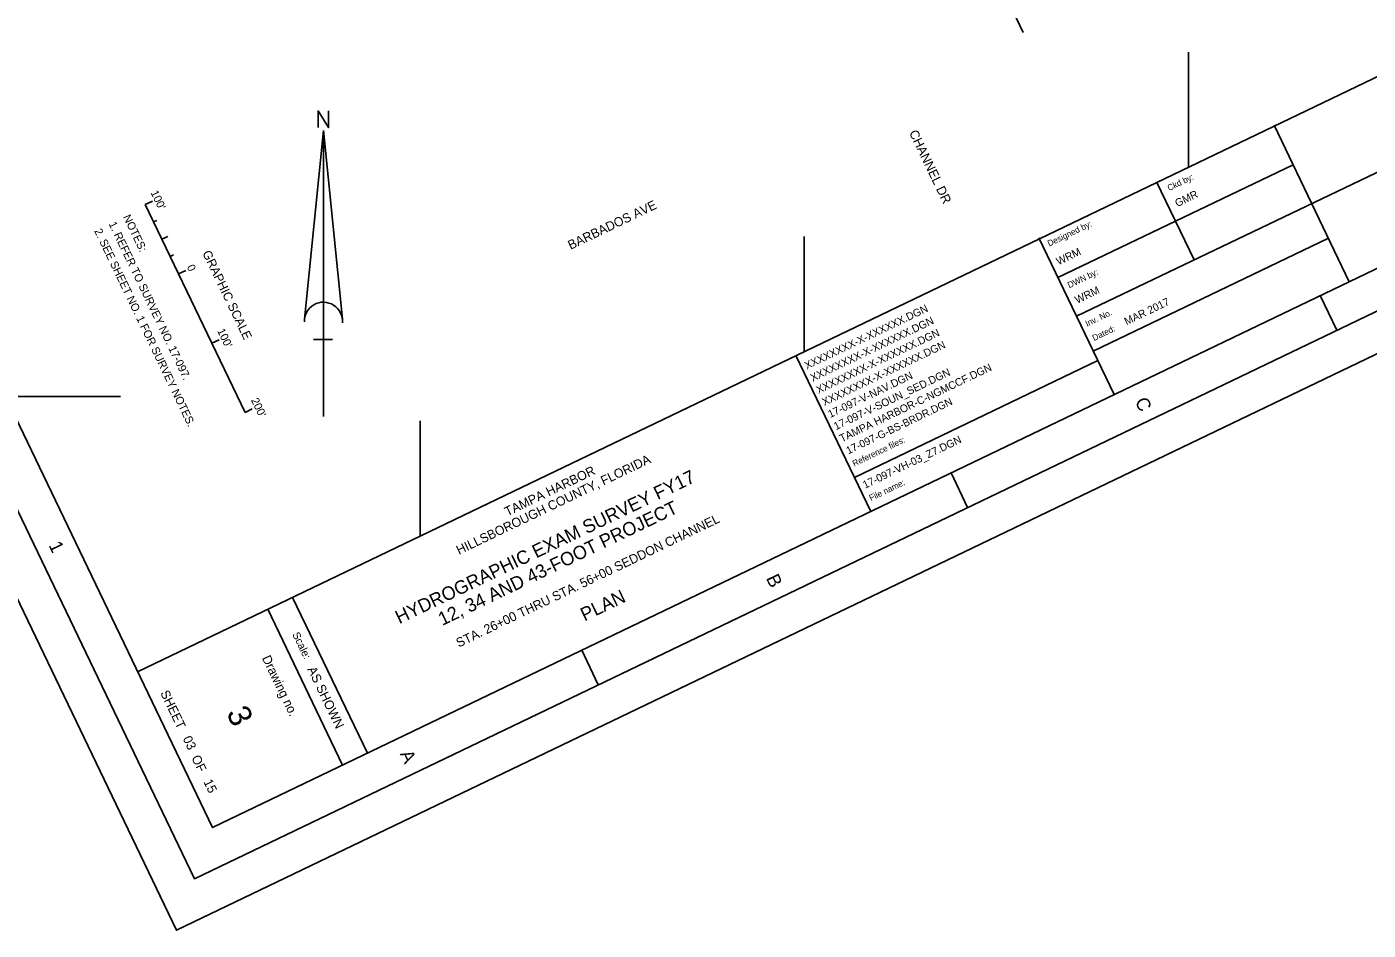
# Model space of a CAD drawing. Extents: x 507278 to 512248, y 1305805 to 1311243.
# Drawn here: x 508988 to 510734, y 1305805 to 1306981 of the extents above; entities that cross this region are included whole.
import ezdxf

# ---------------------------------------------------------------- set-up
doc = ezdxf.new("R2010")
doc.units = 0
for name, color, linetype in [('G-ANNO-NPLT', 7, 'Continuous'), ('G-ANNO-TEXT-DRWG', 7, 'Continuous'), ('G-ANNO-TEXT-PROJ', 7, 'Continuous'), ('G-ANNO-TEXT-TTLB', 7, 'Continuous'), ('G-ANNO-TTLB', 7, 'Continuous'), ('V-ALGN-TEXT', 7, 'Continuous'), ('V-ANNO-NOTE', 7, 'Continuous'), ('V-ANNO-SYMB', 7, 'Continuous'), ('V-ROAD-IDEN', 7, 'Continuous'), ('V-TOPO-COOR-STAT', 7, 'Continuous')]:
    doc.layers.add(name, color=color, linetype=linetype)

msp = doc.modelspace()

# ---------------------------------------------------------------- linework, layer by layer
at = {"layer": 'G-ANNO-NPLT'}
msp.add_lwpolyline([(510343.2, 1311243.3), (512247.6, 1307276.8), (509182.6, 1305805.3), (507278.2, 1309771.7)], close=True, dxfattribs=at)
msp.add_lwpolyline([(509227.7, 1305826.8), (509182.6, 1305805.1), (509161, 1305850.2)], dxfattribs=at)
at = {"layer": 'G-ANNO-TTLB'}
for p, q in [((512016.8, 1307526.6), (509132.1, 1306141.5)), ((510354.3, 1306604.3), (511129.5, 1306975.7)), ((510611.8, 1306852.9), (510709.5, 1306649.3)), ((510330.2, 1306654.7), (510636.4, 1306801.5)), ((510458.7, 1306779.3), (510507.5, 1306677.7)), ((510305.4, 1306706.2), (510403.3, 1306502.3)), ((510682.3, 1306706.1), (510376.1, 1306559)), ((510693.4, 1306586.1), (510671.7, 1306631.1)), ((509989.1, 1306553), (510086.5, 1306350.2)), ((510382, 1306546.7), (510065.2, 1306394.6)), ((510212.6, 1306355.3), (510191, 1306400.3)), ((509333.8, 1306238.4), (509431.2, 1306035.5)), ((509301.6, 1306222.9), (509399, 1306020.1)), ((509731.8, 1306124.4), (509710.2, 1306169.5))]:
    msp.add_line(p, q, dxfattribs=at)
for points in [[(507344.9, 1309748.3), (509206, 1305872), (512180.9, 1307300.3), (510319.8, 1311176.6)], [(512114.2, 1307323.7), (510328.8, 1311042.3), (507444.1, 1309657.3), (509229.5, 1305938.7)]]:
    msp.add_lwpolyline(points, close=True, dxfattribs=at)
at = {"layer": 'V-ALGN-TEXT'}
msp.add_line((510285.1, 1306973.5), (510241.8, 1307063.7), dxfattribs=at)
at = {"layer": 'V-ANNO-NOTE'}
for p, q in [((509142.1, 1306749.6), (509151.5, 1306754.1)), ((509142.1, 1306749.6), (509271.9, 1306479.2)), ((509152.9, 1306727.1), (509157.2, 1306729.1)), ((509163.7, 1306704.5), (509171.4, 1306708.2)), ((509174.5, 1306682), (509178.9, 1306684.1)), ((509185.4, 1306659.5), (509194.8, 1306664)), ((509185.4, 1306659.5), (509194.8, 1306664)), ((509185.4, 1306659.5), (509189.9, 1306661.6)), ((509228.7, 1306569.3), (509238.1, 1306573.8)), ((509271.9, 1306479.2), (509281.4, 1306483.7))]:
    msp.add_line(p, q, dxfattribs=at)
at = {"layer": 'V-ANNO-SYMB'}
for p, q in [((509349.3, 1306600.3), (509374, 1306846)), ((509374, 1306473.7), (509374, 1306846)), ((509398.7, 1306600.3), (509374, 1306846)), ((509385.8, 1306574.2), (509360.9, 1306574.2))]:
    msp.add_line(p, q, dxfattribs=at)
msp.add_lwpolyline([(509367.1, 1306850), (509367.1, 1306871.7), (509380.6, 1306850), (509380.6, 1306871.7)], dxfattribs=at)
msp.add_arc((509374, 1306597.8), 24.8, 355.2984, 182.0673, dxfattribs=at)
at = {"layer": 'V-TOPO-COOR-STAT'}
for p, q in [((510500, 1306798.3), (510500, 1306948.1)), ((510000, 1306558.3), (510000, 1306708)), ((509109.7, 1306500), (508960, 1306500)), ((509500, 1306318.2), (509500, 1306468))]:
    msp.add_line(p, q, dxfattribs=at)

# ---------------------------------------------------------------- texts
at = {"layer": 'G-ANNO-TEXT-DRWG'}
for s, height, rotation, p in [('GMR', 10, 25.6468, (510485.5, 1306746.3)), ('WRM', 10, 25.6468, (510331, 1306670.5)), ('WRM', 10, 25.6468, (510355.3, 1306620.4)), ('XXXXXXXX-X-XXXXXX.DGN', 10, 25.6468, (510003.4, 1306534.8)), ('XXXXXXXX-X-XXXXXX.DGN', 10, 25.6468, (510010.9, 1306519)), ('XXXXXXXX-X-XXXXXX.DGN', 10, 25.6468, (510018.5, 1306503.2)), ('XXXXXXXX-X-XXXXXX.DGN', 10, 25.6468, (510026.1, 1306487.5)), ('17-097-V-NAV.DGN', 10, 25.6468, (510033.7, 1306471.7)), ('17-097-V-SOUN_SED.DGN', 10, 25.6468, (510041.2, 1306455.9)), ('TAMPA HARBOR-C-NGMCCF.DGN', 10, 25.6468, (510048.8, 1306440.1)), ('17-097-VH-03_Z7.DGN', 10, 25.6468, (510079, 1306379.6)), ('STA. 26+00 THRU STA. 56+00 SEDDON CHANNEL', 12, 25.6468, (509550.2, 1306172.9)), ('PLAN', 17.5, 25.6468, (509713.9, 1306206.9)), ('3', 30, 295.6468, (509247.1, 1306087.9)), (' 03          15', 12, 295.6468, (509188.6, 1306058.6))]:
    msp.add_text(s, height=height, rotation=rotation, dxfattribs=at).set_placement(p)
at = {"layer": 'G-ANNO-TEXT-PROJ'}
for s, height, p in [('MAR 2017', 10, (510419.5, 1306592.4)), ('17-097-G-BS-BRDR.DGN', 9.8, (510057.3, 1306424.4)), ('HILLSBOROUGH COUNTY, FLORIDA', 12, (509550.5, 1306293.6)), ('HYDROGRAPHIC EXAM SURVEY FY17', 17.5, (509472.8, 1306203.4)), ('TAMPA HARBOR', 12, (509613.4, 1306343.7)), ('12, 34 AND 43-FOOT PROJECT', 17.5, (509528.7, 1306201.1))]:
    msp.add_text(s, height=height, rotation=25.6468, dxfattribs=at).set_placement(p)
at = {"layer": 'G-ANNO-TEXT-TTLB'}
for s, height, rotation, p in [('Ckd by:', 8, 25.6468, (510475, 1306767.2)), ('Designed by:', 8, 25.6468, (510318.9, 1306694.9)), ('DWN by:', 8, 25.6468, (510345, 1306640.6)), ('Inv. No.', 8, 25.6468, (510368.2, 1306590.5)), ('Dated:', 8, 25.6468, (510377.3, 1306571.8)), ('Reference files:', 8, 25.6468, (510065, 1306408.5)), ('File name:', 8, 25.6468, (510086.8, 1306363.6)), ('Scale:', 10, 295.6468, (509333.2, 1306190.3)), ('Drawing no.', 12, 295.6468, (509293.6, 1306159.4)), ('AS SHOWN', 12, 295.6468, (509352.8, 1306144.9)), ('SHEET         OF', 12, 295.6468, (509161.3, 1306114))]:
    msp.add_text(s, height=height, rotation=rotation, dxfattribs=at).set_placement(p)
at = {"layer": 'G-ANNO-TTLB'}
for s, p in [('C', (510430, 1306493.7)), ('1', (509015.9, 1306306.4)), ('B', (509949.8, 1306263.4)), ('A', (509473.1, 1306034.6))]:
    msp.add_text(s, height=17.5, rotation=295.6468, dxfattribs=at).set_placement(p)
at = {"layer": 'V-ANNO-NOTE'}
for s, height, p in [("100'", 10.42, (509148.7, 1306765.3)), ('NOTES:', 10.42, (509112.9, 1306733.6)), ('2. SEE SHEET NO. 1 FOR SURVEY NOTES.', 10.416, (509075.3, 1306715.6)), ('1. REFER TO SURVEY NO. 17-097.', 10.416, (509094.1, 1306724.6)), ('GRAPHIC SCALE', 11.666, (509216.1, 1306686.6)), ('0', 10.4, (509195.9, 1306668.6)), ("100'", 10.42, (509235.4, 1306585.5)), ("200'", 10.42, (509279.4, 1306495.1))]:
    msp.add_text(s, height=height, rotation=295.6468, dxfattribs=at).set_placement(p)
at = {"layer": 'V-ROAD-IDEN'}
for s, rotation, p in [('CHANNEL DR', 295.6468, (510136.1, 1306843.3)), ('BARBADOS AVE', 25.6468, (509695.8, 1306690.7))]:
    msp.add_text(s, height=12, rotation=rotation, dxfattribs=at).set_placement(p)

doc.saveas('drawing.dxf')
